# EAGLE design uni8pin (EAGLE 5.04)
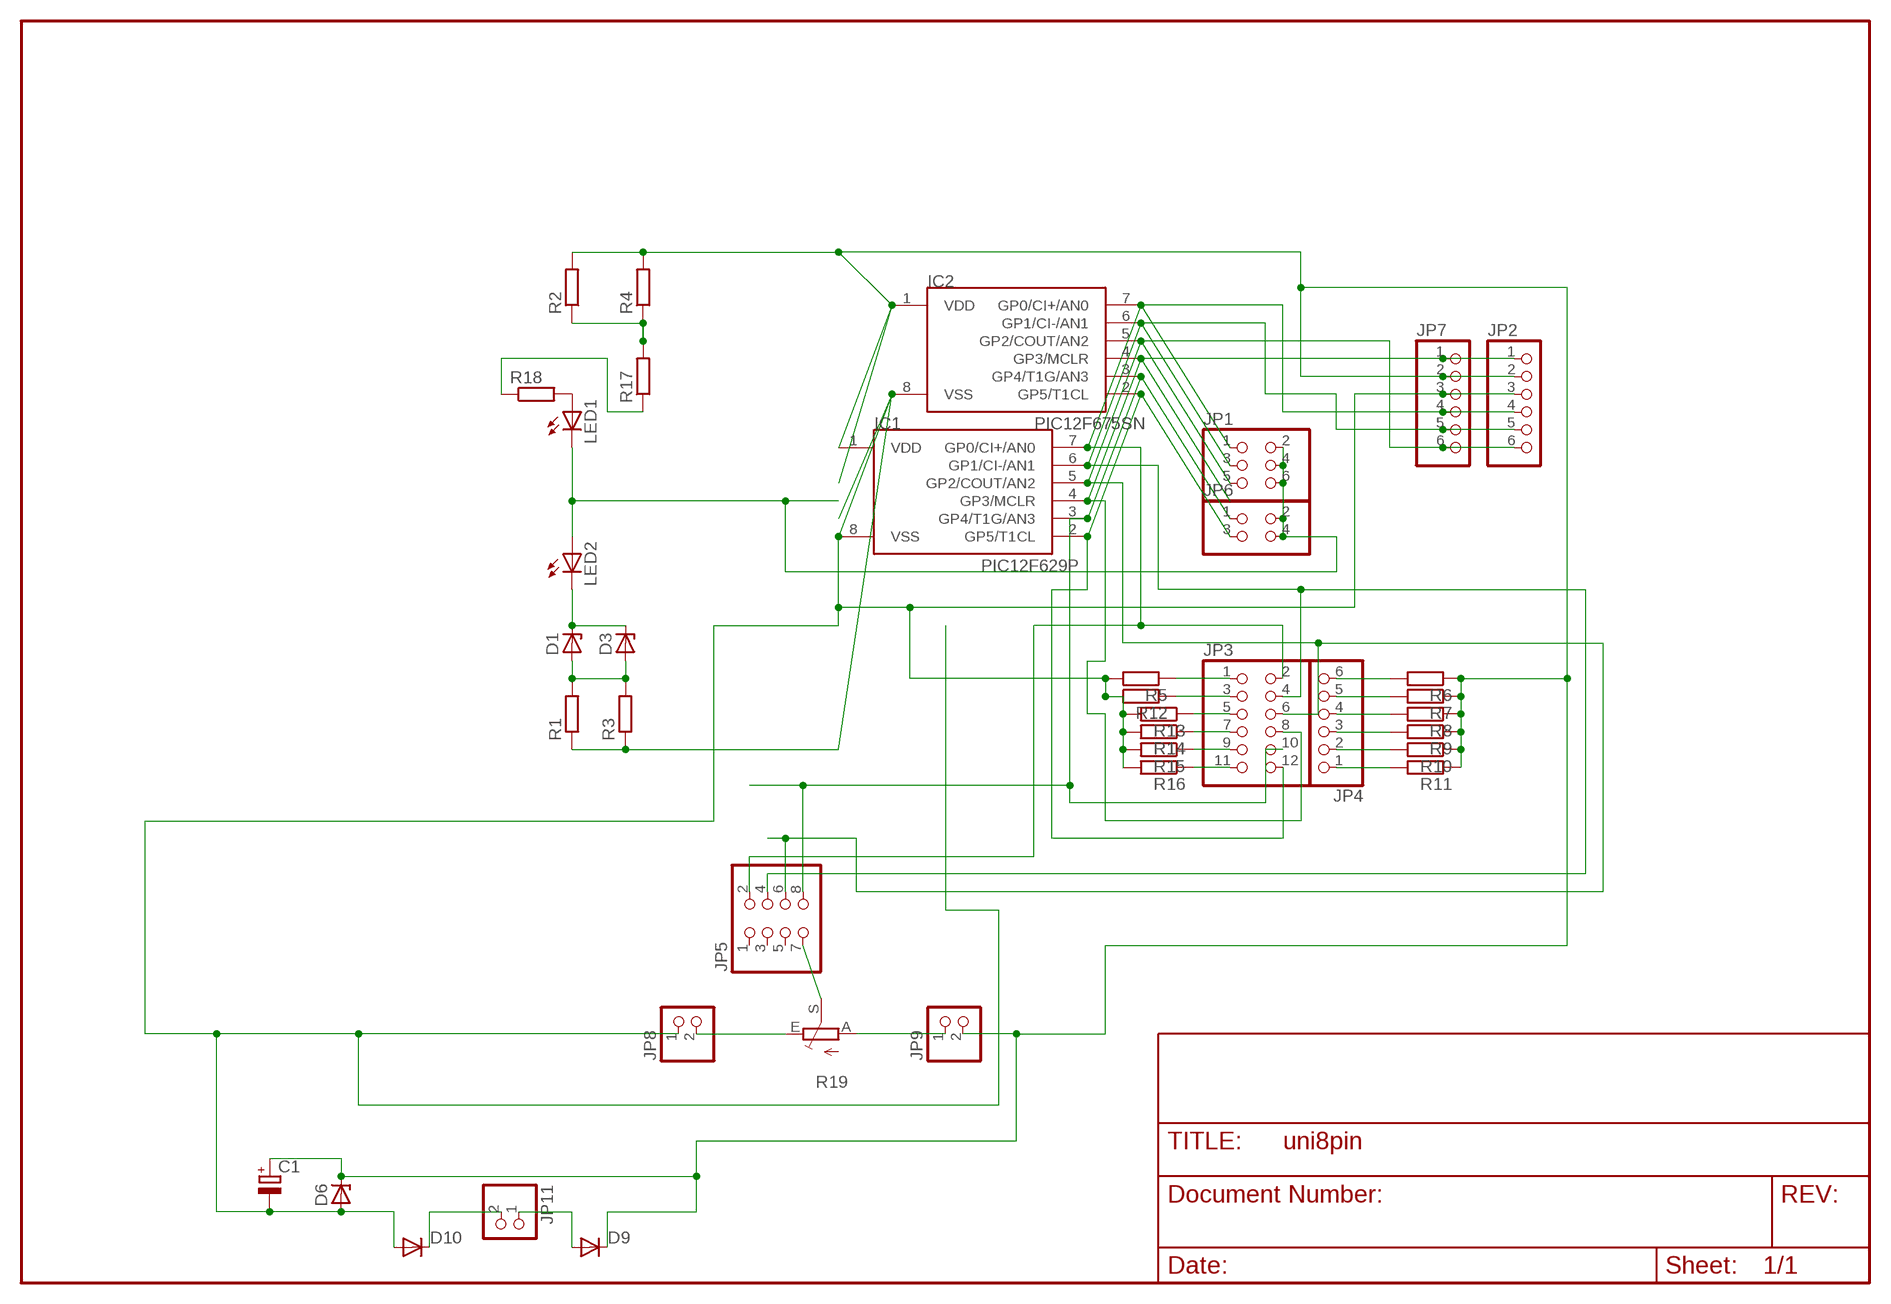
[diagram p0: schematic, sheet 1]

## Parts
C1  CPOL-EU5-13  [2,5-5-FLAT]
D1  ZENER-DIODESOT23  [SOT23]
D3  ZENER-DIODEZD-2.5  [ZDIO-2.5]
D6  ZENER-DIODEZD-2.5  [ZDIO-2.5]
D9  DIODE-D-5  [D-5]
D10  DIODE-D-5  [D-5]
IC1  PIC12F629P  [DIL8]
IC2  PIC12F675SN  [SO-08]
JP1  PINHD-2X3  [2X03]
JP2  PINHD-1X6  [1X06]
JP3  PINHD-2X6  [2X06]
JP4  PINHD-1X6  [1X06]
JP5  PINHD-2X4  [2X04]
JP6  PINHD-2X2  [2X02]
JP7  PINHD-1X6  [1X06]
JP8  PINHD-1X2  [1X02]
JP9  PINHD-1X2  [1X02]
JP11  PINHD-1X2  [1X02]
LED1  LED5MM  [LED5MM]
LED2  LED5MM  [LED5MM]
R1  R-EU_0204/2V  [0204V]
R2  R-EU_0204/2V  [0204V]
R3  R-EU_R1206  [R1206]
R4  R-EU_R1206  [R1206]
R5  R-EU_R1206  [R1206]
R6  R-EU_R1206  [R1206]
R7  R-EU_R1206  [R1206]
R8  R-EU_R1206  [R1206]
R9  R-EU_R1206  [R1206]
R10  R-EU_R1206  [R1206]
R11  R-EU_R1206  [R1206]
R12  R-EU_R1206  [R1206]
R13  R-EU_R1206  [R1206]
R14  R-EU_R1206  [R1206]
R15  R-EU_R1206  [R1206]
R16  R-EU_R1206  [R1206]
R17  R-EU_R1206  [R1206]
R18  R-EU_R1206  [R1206]
R19  TRIM_EU-CA6V  [CA6V]

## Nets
N$1: IC1.3(GP4/T1G/AN3) IC2.3(GP4/T1G/AN3) JP3.10 JP5.8 JP6.1
N$2: D1.3(C) D3.C LED2.K(C)
N$3: D1.1(A) D3.A R1.2 R3.2
N$4: JP1.2 JP1.4 JP1.6 JP6.2 JP6.4 LED1.K(C) LED2.A
N$5: C1.- D6.A D10.A IC1.8(VSS) IC2.8(VSS) JP2.3 JP7.3 JP8.1 R1.1 R3.1 R5.2 R12.2 R13.2 R14.2 R15.2 R16.2
N$6: C1.+ D6.C D9.C IC1.1(VDD) IC2.1(VDD) JP2.2 JP7.2 JP9.2 R2.2 R4.2 R6.1 R7.1 R8.1 R9.1 R10.1 R11.1
N$7: R2.1 R4.1 R17.2
N$8: R17.1 R18.1
N$9: IC1.2(GP5/T1CL) IC2.2(GP5/T1CL) JP3.12 JP6.3
N$10: LED1.A R18.2
N$11: IC1.4(GP3/MCLR) IC2.4(GP3/MCLR) JP2.1 JP3.8 JP7.1
N$12: IC1.5(GP2/COUT/AN2) IC2.5(GP2/COUT/AN2) JP1.5 JP2.6 JP3.6 JP5.6 JP7.6
N$13: IC1.6(GP1/CI-/AN1) IC2.6(GP1/CI-/AN1) JP1.3 JP2.5 JP3.4 JP5.4 JP7.5
N$14: IC1.7(GP0/CI+/AN0) IC2.7(GP0/CI+/AN0) JP1.1 JP2.4 JP3.2 JP5.2 JP7.4
N$15: JP4.6 R6.2
N$16: JP4.5 R7.2
N$17: JP4.4 R8.2
N$18: JP4.3 R9.2
N$19: JP4.2 R10.2
N$20: JP4.1 R11.2
N$21: JP3.1 R5.1
N$22: JP3.3 R12.1
N$23: JP3.5 R13.1
N$24: JP3.7 R14.1
N$25: JP3.9 R15.1
N$26: JP3.11 R16.1
N$31: JP9.1 R19.A
N$32: JP8.2 R19.E
N$33: JP5.7 R19.S
N$34: D10.C JP11.2
N$35: D9.A JP11.1
Unconnected: JP5.1 JP5.3 JP5.5

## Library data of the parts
C1 = rcl-2:CPOL-EU: POLARIZED CAPACITOR, European symbol
D1 D3 D6 = diode-1:ZENER-DIODE: Z-Diode
D9 D10 = diode-1:DIODE-: DIODE
IC1 IC2 = microchip-5:PIC12F6*: uPC nW 1k Program Flash memory 2x Timer Comparator 10b A/D converter/ 4xIN
JP1 = pinhead(2):PINHD-2X3: PIN HEADER
JP2 JP7 = pinhead:PINHD-1X6: PIN HEADER
JP3 = pinhead(2):PINHD-2X6: PIN HEADER
JP4 = pinhead(2):PINHD-1X6: PIN HEADER
JP5 = pinhead(2):PINHD-2X4: PIN HEADER
JP6 = pinhead(2):PINHD-2X2: PIN HEADER
JP8 JP9 JP11 = pinhead(2):PINHD-1X2: PIN HEADER
LED1 LED2 = led:LED: LED
R1-R18 = rcl-2:R-EU_: RESISTOR, European symbol
R19 = pot:TRIM_EU-: POTENTIOMETER

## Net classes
0 default: width 0.3 mm, drill 0.6 mm, clearance 0.2 mm
1 power: width 0.4 mm, drill 0.6 mm, clearance 0.2 mm

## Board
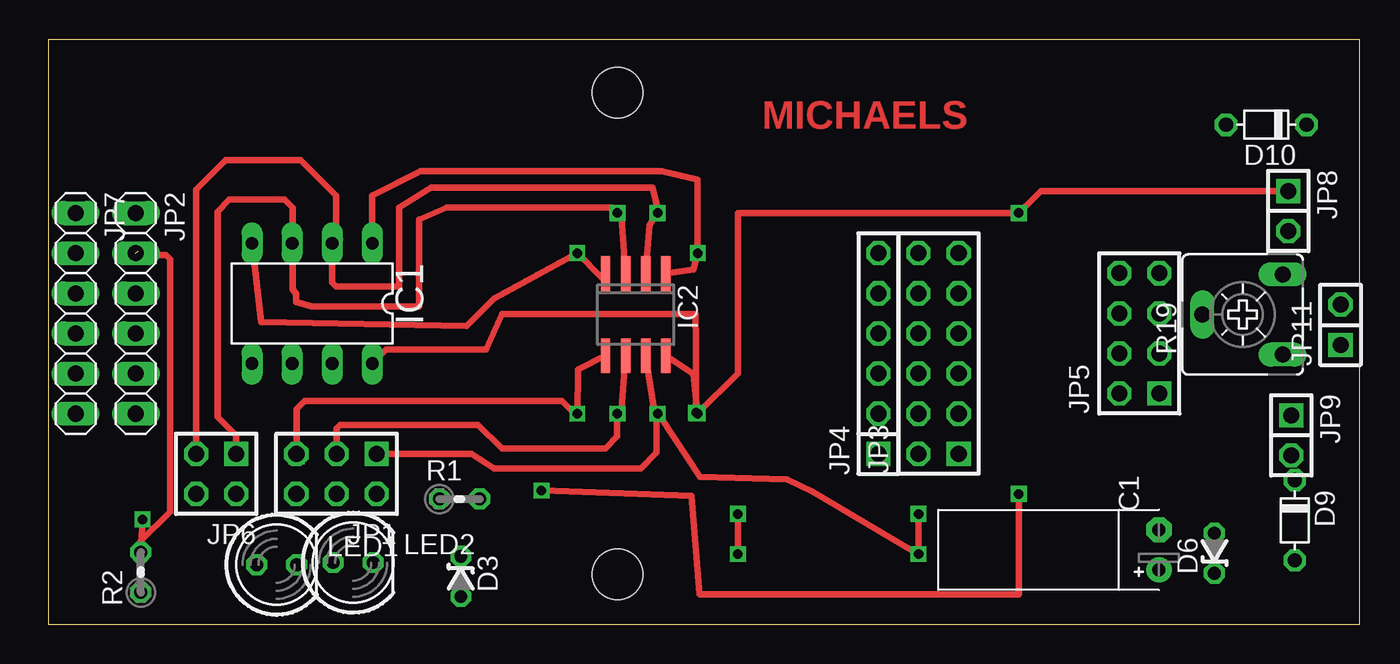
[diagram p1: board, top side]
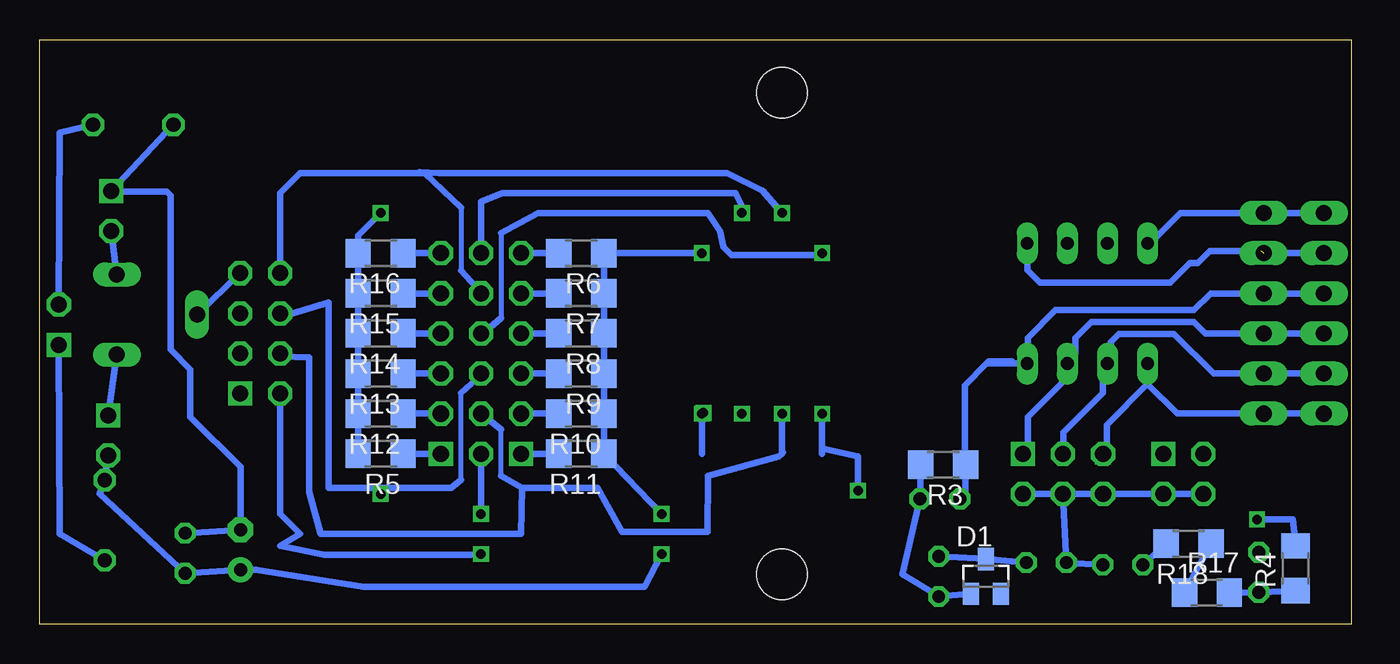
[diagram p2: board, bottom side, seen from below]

Size 83.02 x 37.02 mm. Coordinates in mm from the lower left corner, seen from the top.
Outline: 0,0 83.02,0 83.02,37.02 0,37.02 0,0
Copper layers (1*16): Top 0.035mm / dielectric 1.5mm / Bottom 0.035mm
Design rules "default": minimum track width 10mil, minimum drill 24mil, track to track 8mil, track to pad 8mil, pad to pad 8mil, via to via 8mil, smd to smd 8mil, copper to edge 40mil, drill to drill 8mil, minimum pad ring 10mil, minimum via ring 8mil, stop-mask expansion 4mil, vias tented up to drill 0mil, thermal gap 10mil
Holes 3.2 mm at 36.03,33.65 36.03,3.17

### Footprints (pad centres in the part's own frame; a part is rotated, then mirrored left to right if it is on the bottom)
2,5-5-FLAT = drill 0.813 pad 1.6 round: + -1.27,0 | drill 0.813 pad 1.6 octagon: - 1.27,0
SOT23 = smd 1 x 1.4: 1 -0.95,-1.1; 2 0.95,-1.1; 3 0,1.1
ZDIO-2.5 = drill 0.813 octagon: A 1.27,0; C -1.27,0
D-5 = drill 0.9 octagon: A 2.54,0; C -2.54,0
DIL8 = drill 0.813 long: 1 -3.81,-3.81; 2 -1.27,-3.81; 3 1.27,-3.81; 4 3.81,-3.81; 5 3.81,3.81; 6 1.27,3.81; 7 -1.27,3.81; 8 -3.81,3.81
SO-08 = smd 0.6 x 2.2: 1 -1.905,-2.6; 2 -0.635,-2.6; 3 0.635,-2.6; 4 1.905,-2.6; 5 1.905,2.6; 6 0.635,2.6; 7 -0.635,2.6; 8 -1.905,2.6
2X03 = drill 1.016 square: 1 -2.54,-1.27 | drill 1.016 octagon: 2 -2.54,1.27; 3 0,-1.27; 4 0,1.27; 5 2.54,-1.27; 6 2.54,1.27
1X06 = drill 1.016 long: 1 -6.35,0; 2 -3.81,0; 3 -1.27,0; 4 1.27,0; 5 3.81,0; 6 6.35,0
2X06 = drill 1.016 square: 1 -6.35,-1.27 | drill 1.016 octagon: 2 -6.35,1.27; 3 -3.81,-1.27; 4 -3.81,1.27; 5 -1.27,-1.27; 6 -1.27,1.27; 7 1.27,-1.27; 8 1.27,1.27; 9 3.81,-1.27; 10 3.81,1.27; 11 6.35,-1.27; 12 6.35,1.27
1X06' = drill 1.016 square: 1 -6.35,0 | drill 1.016 octagon: 2 -3.81,0; 3 -1.27,0; 4 1.27,0; 5 3.81,0; 6 6.35,0
2X04 = drill 1.016 square: 1 -3.81,-1.27 | drill 1.016 octagon: 2 -3.81,1.27; 3 -1.27,-1.27; 4 -1.27,1.27; 5 1.27,-1.27; 6 1.27,1.27; 7 3.81,-1.27; 8 3.81,1.27
2X02 = drill 1.016 square: 1 -1.27,-1.27 | drill 1.016 octagon: 2 -1.27,1.27; 3 1.27,-1.27; 4 1.27,1.27
1X02 = drill 1.016 square: 1 -1.27,0 | drill 1.016 octagon: 2 1.27,0
LED5MM = drill 0.813 octagon: A -1.27,0; K 1.27,0
0204V = drill 0.813 octagon: 1 -1.27,0; 2 1.27,0
R1206 = smd 1.6 x 1.803: 1 -1.422,0; 2 1.422,0
CA6V = drill 1.016 long: A -2.54,-2.54; E 2.54,-2.54; S 0,2.54

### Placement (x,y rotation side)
C1  70.3,4.71 90 top
D1  23.12,3.03 0 bottom
D3  26.11,3.03 270 top
D6  73.81,4.5 90 top
D9  78.89,6.58 270 top
D10  77.09,31.62 180 top
IC1  16.71,20.31 180 top
IC2  37.18,19.6 180 top
JP1  18.25,9.52 180 top
JP2  5.55,19.68 270 top
JP3  56.35,17.14 90 top
JP4  [1X06']  52.54,17.14 90 top
JP5  69.05,18.41 90 top
JP6  10.63,9.52 180 top
JP7  1.74,19.68 270 top
JP8  78.48,26.15 270 top
JP9  78.67,11.95 270 top
JP11  81.79,18.96 90 top
LED1  14.46,3.77 0 top
LED2  19.3,3.9 0 top
R1  26.03,7.94 0 top
R2  5.86,3.29 90 top
R3  25.83,10.11 180 bottom
R4  3.53,3.55 90 bottom
R5  61.43,10.79 180 bottom
R6  48.73,23.49 180 bottom
R7  48.73,20.95 180 bottom
R8  48.73,18.41 180 bottom
R9  48.73,15.87 180 bottom
R10  48.73,13.33 180 bottom
R11  48.73,10.79 180 bottom
R12  61.43,13.33 180 bottom
R13  61.43,15.87 180 bottom
R14  61.43,18.41 180 bottom
R15  61.43,20.95 180 bottom
R16  61.43,23.49 180 bottom
R17  9.14,2 0 bottom
R18  10.31,5.09 180 bottom
R19  75.59,19.61 90 top

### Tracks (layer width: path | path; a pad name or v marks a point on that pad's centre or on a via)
N$1  (via drill 0.6)
  Top 0.406: JP6.1 11.9,11.95 10.72,13.13 10.72,26.13 11.47,26.88 14.97,26.88 15.47,26.38 | IC1.3 15.44,23.91 15.47,23.88 15.47,26.38 | IC2.3 36.3,25.77 v36.03,26.03 36.07,26.03 | 15.47,26.38 15.47,21.19 15.71,20.95 15.71,20.39 16.72,20.13 23.47,20.13 23.47,25.63 25.22,26.38 35.72,26.38 36.07,26.03 | 36.07,26.03 36.22,25.88
  Bottom 0.305: 56.35,26.38 56.35,22.38
  Bottom 0.406: JP5.8 67.78,27.3 66.51,28.57 58.97,28.57 | 58.97,28.57 58.66,28.57 56.35,26.38 | JP3.10 55.08,20.99 56.35,22.38 | v36.03,26.03 37.28,27.44 39.51,28.57 57.72,28.57 58.97,28.63 58.97,28.57
N$2
  Bottom 0.406: LED2.K D1.3 D3.C
N$3
  Bottom 0.406: D1.1 D3.A 28.41,3.17 R1.2 R3.2
N$4
  Bottom 0.406: LED1.K LED2.A JP1.4 | JP1.4 JP1.6 JP6.2 JP6.4 | JP1.4 JP1.2
N$5  (via drill 0.6)
  Top 0.406: IC2.8 40.84,15.86 v41.11,13.33 43.65,15.87 43.65,26.03 v61.43,26.03 62.82,27.42 JP8.1 | v41.01,13.38 41.01,17.84 40.97,19.63 28.72,19.63 27.72,17.38 21.4,17.38 IC1.8
  Bottom 0.406: IC1.8 20.35,16.5 20.22,16.63 20.47,16.88 20.47,18.13 18.72,19.88 9.97,19.88 8.9,20.95 JP2.3 JP7.3 | 41.11,10.79 v41.11,13.33 41.06,13.33 v41.01,13.38 | 23.1,16.5 24.47,15.13 24.47,10.38 24.41,10.32 R3.1 24.41,8.44 24.76,8.09 R1.1 | IC1.8 23.1,16.5 | IC1.8 21.34,16.5 21.47,16.63 22.97,16.63 23.1,16.5 | v61.43,26.03 62.85,24.61 R16.2 R15.2 R14.2 R13.2 R12.2 R5.2 | 78.51,27.42 78.72,27.63 | 78.51,27.42 JP8.1 D10.A | 78.51,27.42 78.47,27.38 74.97,27.38 74.72,27.13 74.72,17.38 73.47,16.13 73.47,13.13 70.3,9.96 C1.- D6.A
N$6  (via drill 0.6)  (2 unrouted)
  Top 0.406: 5.47,23.38 7.47,23.38 7.72,23.13 7.72,7.13 5.86,5.27 R2.2 v5.97,6.63 | 5.47,23.38 5.22,23.38 4.97,23.63 5.22,23.63 5.47,23.38 | 5.47,23.38 5.55,23.46 | IC2.1 40.84,22.46 v41.11,23.49 41.11,28.15 38.82,28.69 23.58,28.69 20.52,27.13 IC1.1 | v43.65,6.98 v43.65,4.44
  Bottom 0.406: 47.4,20.95 47.31,21.04 R6.1 v41.11,23.49 | 47.27,13.33 47.22,13.38 | 47.27,13.33 R10.1 47.31,15.72 47.46,15.87 | 47.27,13.33 47.31,13.29 R11.1 v43.65,6.98 | 47.46,15.87 47.47,15.88 | 47.46,15.87 R9.1 R8.1 | R8.1 47.31,18.54 47.22,18.63 | 47.4,20.95 47.47,20.88 47.31,20.72 R8.1 | 47.4,20.95 R7.1 | IC1.1 20.52,22.43 19.72,21.63 11.47,21.63 10.22,22.88 9.72,22.88 8.97,23.63 5.69,23.63 | v43.65,4.44 44.73,2.38 62.51,2.38 69.32,3.44 C1.+ D6.C 79.21,8.25 D9.C JP9.2 | R4.2 3.72,6.63 v5.97,6.63 | JP7.2 JP2.2
N$7
  Bottom 0.406: R4.1 R2.1 R17.2
N$8
  Bottom 0.406: R17.1 R18.1
N$9  (via drill 0.6)
  Top 0.406: IC2.2 38.06,25.27 v38.57,26.03 38.57,26.07 38.51,26.13 38.51,26.59 38.26,27.63 24.22,27.63 22.22,26.38 22.22,21.38 18.22,21.38 17.98,21.62 IC1.2 17.98,23.89 | JP6.3 9.36,27.52 11.22,29.38 15.97,29.38 18.22,27.13 18.22,24.63 18.47,24.38 17.98,23.89 | 17.98,23.89 17.97,23.88
  Bottom 0.406: JP3.12 55.08,26.77 53.72,27.3 38.97,27.3 38.57,26.47 v38.57,26.03
N$10
  Bottom 0.406: R18.2 LED1.A
N$11  (via drill 0.6)
  Top 0.406: IC2.4 35.02,21.95 v33.49,23.49 28.22,20.63 26.47,18.88 13.47,19.13 IC1.4
  Bottom 0.305: 53.81,24.76 53.81,19.38
  Bottom 0.406: 12.9,23.95 12.97,23.88 | IC1.4 12.9,23.95 | 12.9,23.95 10.82,26.03 JP2.1 JP7.1 | JP3.8 54.94,18.41 53.81,19.38 | 53.81,24.76 51.47,26.03 40.72,26.03 39.97,24.88 39.72,23.88 39.22,23.38 33.22,23.38 33.33,23.49 v33.49,23.49
N$12  (via drill 0.6)
  Top 0.406: IC2.5 33.52,16.11 v33.49,13.33 33.49,13.15 | v15.72,10.63 15.72,13.63 16.22,14.13 32.51,14.13 33.49,13.15 | 33.49,13.15 33.51,13.13 | v61.43,8.25 61.43,1.9 41.22,1.9 40.72,8.13 v31.22,8.46
  Bottom 0.305: 56.35,9.13 56.35,14.63
  Bottom 0.406: v33.49,13.33 33.49,11.13 | 33.49,11.13 33.49,10.79 | 12.9,15.2 IC1.5 | 12.9,15.2 15.47,12.63 15.47,10.88 v15.71,10.64 | v15.72,10.63 v15.71,10.64 | v15.71,10.64 JP1.5 | JP5.6 67.02,19.68 64.72,20.38 64.72,8.63 61.18,8.63 | 61.18,8.63 56.97,8.63 56.35,9.13 | 33.49,11.13 31.22,10.63 v31.22,8.46 | JP3.6 55.08,15.77 56.35,14.63 | v61.43,8.25 61.18,8.63 | JP7.6 JP2.6 11.02,13.33 12.9,15.2
N$13  (via drill 0.6)
  Top 0.406: IC2.6 36.3,13.6 v36.03,13.33 36.06,13.33 36.26,13.13 36.01,12.88 36.01,11.88 35.26,11.13 28.72,11.13 27.22,12.63 18.47,12.63 18.25,12.41 JP1.3
  Bottom 0.305: 53.81,9.38 53.81,12.33
  Bottom 0.406: 15.6,16.5 15.72,16.38 15.72,14.63 18.22,12.13 18.22,10.63 18.25,10.66 JP1.3 | 15.6,16.5 IC1.6 | 15.6,16.5 15.22,16.88 15.22,17.88 14.72,18.38 11.22,18.38 8.71,15.87 JP2.5 JP7.5 | v36.03,13.33 36.03,10.88 | 36.03,10.88 36.03,10.79 | 55.08,12.99 JP3.4 53.81,12.33 | JP5.4 67.78,16.94 65.97,16.88 65.97,8.38 65.24,5.71 52.54,5.71 52.47,8.63 | 52.47,8.63 53.81,9.38 | 52.47,8.63 47.72,8.63 46.14,5.84 40.76,5.84 40.72,9.38 36.22,10.63 35.97,10.88 36.03,10.88
N$14  (via drill 0.6)
  Top 0.406: IC2.7 38.31,13.84 v38.57,13.33 v38.57,13.32 38.76,13.13 | JP1.1 26.81,10.79 28.22,9.88 37.51,9.88 38.51,10.88 38.51,12.88 38.76,13.13 | 38.76,13.13 41.26,9.34 46.76,9.17 48.39,8.38 v55.08,4.44 v55.08,6.98
  Bottom 0.406: JP1.1 20.79,10.81 20.47,11.13 20.47,13.13 17.98,15.62 IC1.7 17.98,16.62 17.47,17.13 17.47,18.13 16.47,19.13 9.97,19.13 9.25,18.41 JP2.4 JP7.4 | JP5.2 67.78,6.98 66.51,5.71 67.8,4.96 64.97,4.38 55.72,4.38 v55.08,4.44 | v55.08,6.98 JP3.2
N$15
  Bottom 0.406: R6.2 JP4.6
N$16
  Bottom 0.406: R7.2 JP4.5
N$17
  Bottom 0.406: R8.2 JP4.4
N$18
  Bottom 0.406: R9.2 JP4.3
N$19
  Bottom 0.406: R10.2 JP4.2
N$20
  Bottom 0.406: R11.2 JP4.1
N$21
  Bottom 0.406: JP3.1 R5.1
N$22
  Bottom 0.406: JP3.3 R12.1
N$23
  Bottom 0.406: JP3.5 R13.1
N$24
  Bottom 0.406: JP3.7 R14.1
N$25
  Bottom 0.406: JP3.9 R15.1
N$26
  Bottom 0.406: JP3.11 R16.1
N$31
  Bottom 0.406: JP9.1 R19.A
N$32
  Bottom 0.406: R19.E JP8.2
N$33
  Bottom 0.406: JP5.7 R19.S
N$34
  Bottom 0.406: JP11.2 81.75,31.11 D10.C
N$35
  Bottom 0.406: D9.A 81.75,5.71 JP11.1

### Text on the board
Top: MICHAELS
